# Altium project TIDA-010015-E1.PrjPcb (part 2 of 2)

## Sheet TIDA-010015-LLC.SchDoc: LLC
size 431 x 317 mm; Date: Not shown in title block; ApprovedBy: Not shown in title block; CheckedBy: Not shown in title block; Author: Not shown in title block; CompanyName: Not shown in title block; DrawnBy: Ramkumar S; Engineer: Ramkumar S; Organization: Not shown in title block; Address1: Not shown in title block; Address2: Not shown in title block; Address3: Not shown in title block; Address4: Not shown in title block; DocumentNumber: 1; Revision: Use project parameter SCH_Rev; SheetNumber: 3; SheetTotal: 4; PageSetup: Record=PageOptions¦CenterHorizontal=True¦CenterVertical=True¦PrintScale=1.00¦XCorrection=1.00¦YCorrection=1.00¦PrintKind=0¦BorderSize=5000000¦LeftOffset=0¦BottomOffset=0¦Orientation=2¦PaperLength=1000¦PaperWidth=1000¦Scale=100¦PaperSource=15¦PrintQuality=600¦MediaType=1¦DitherType=10¦PaperKind=Letter¦PrintScaleMode=1
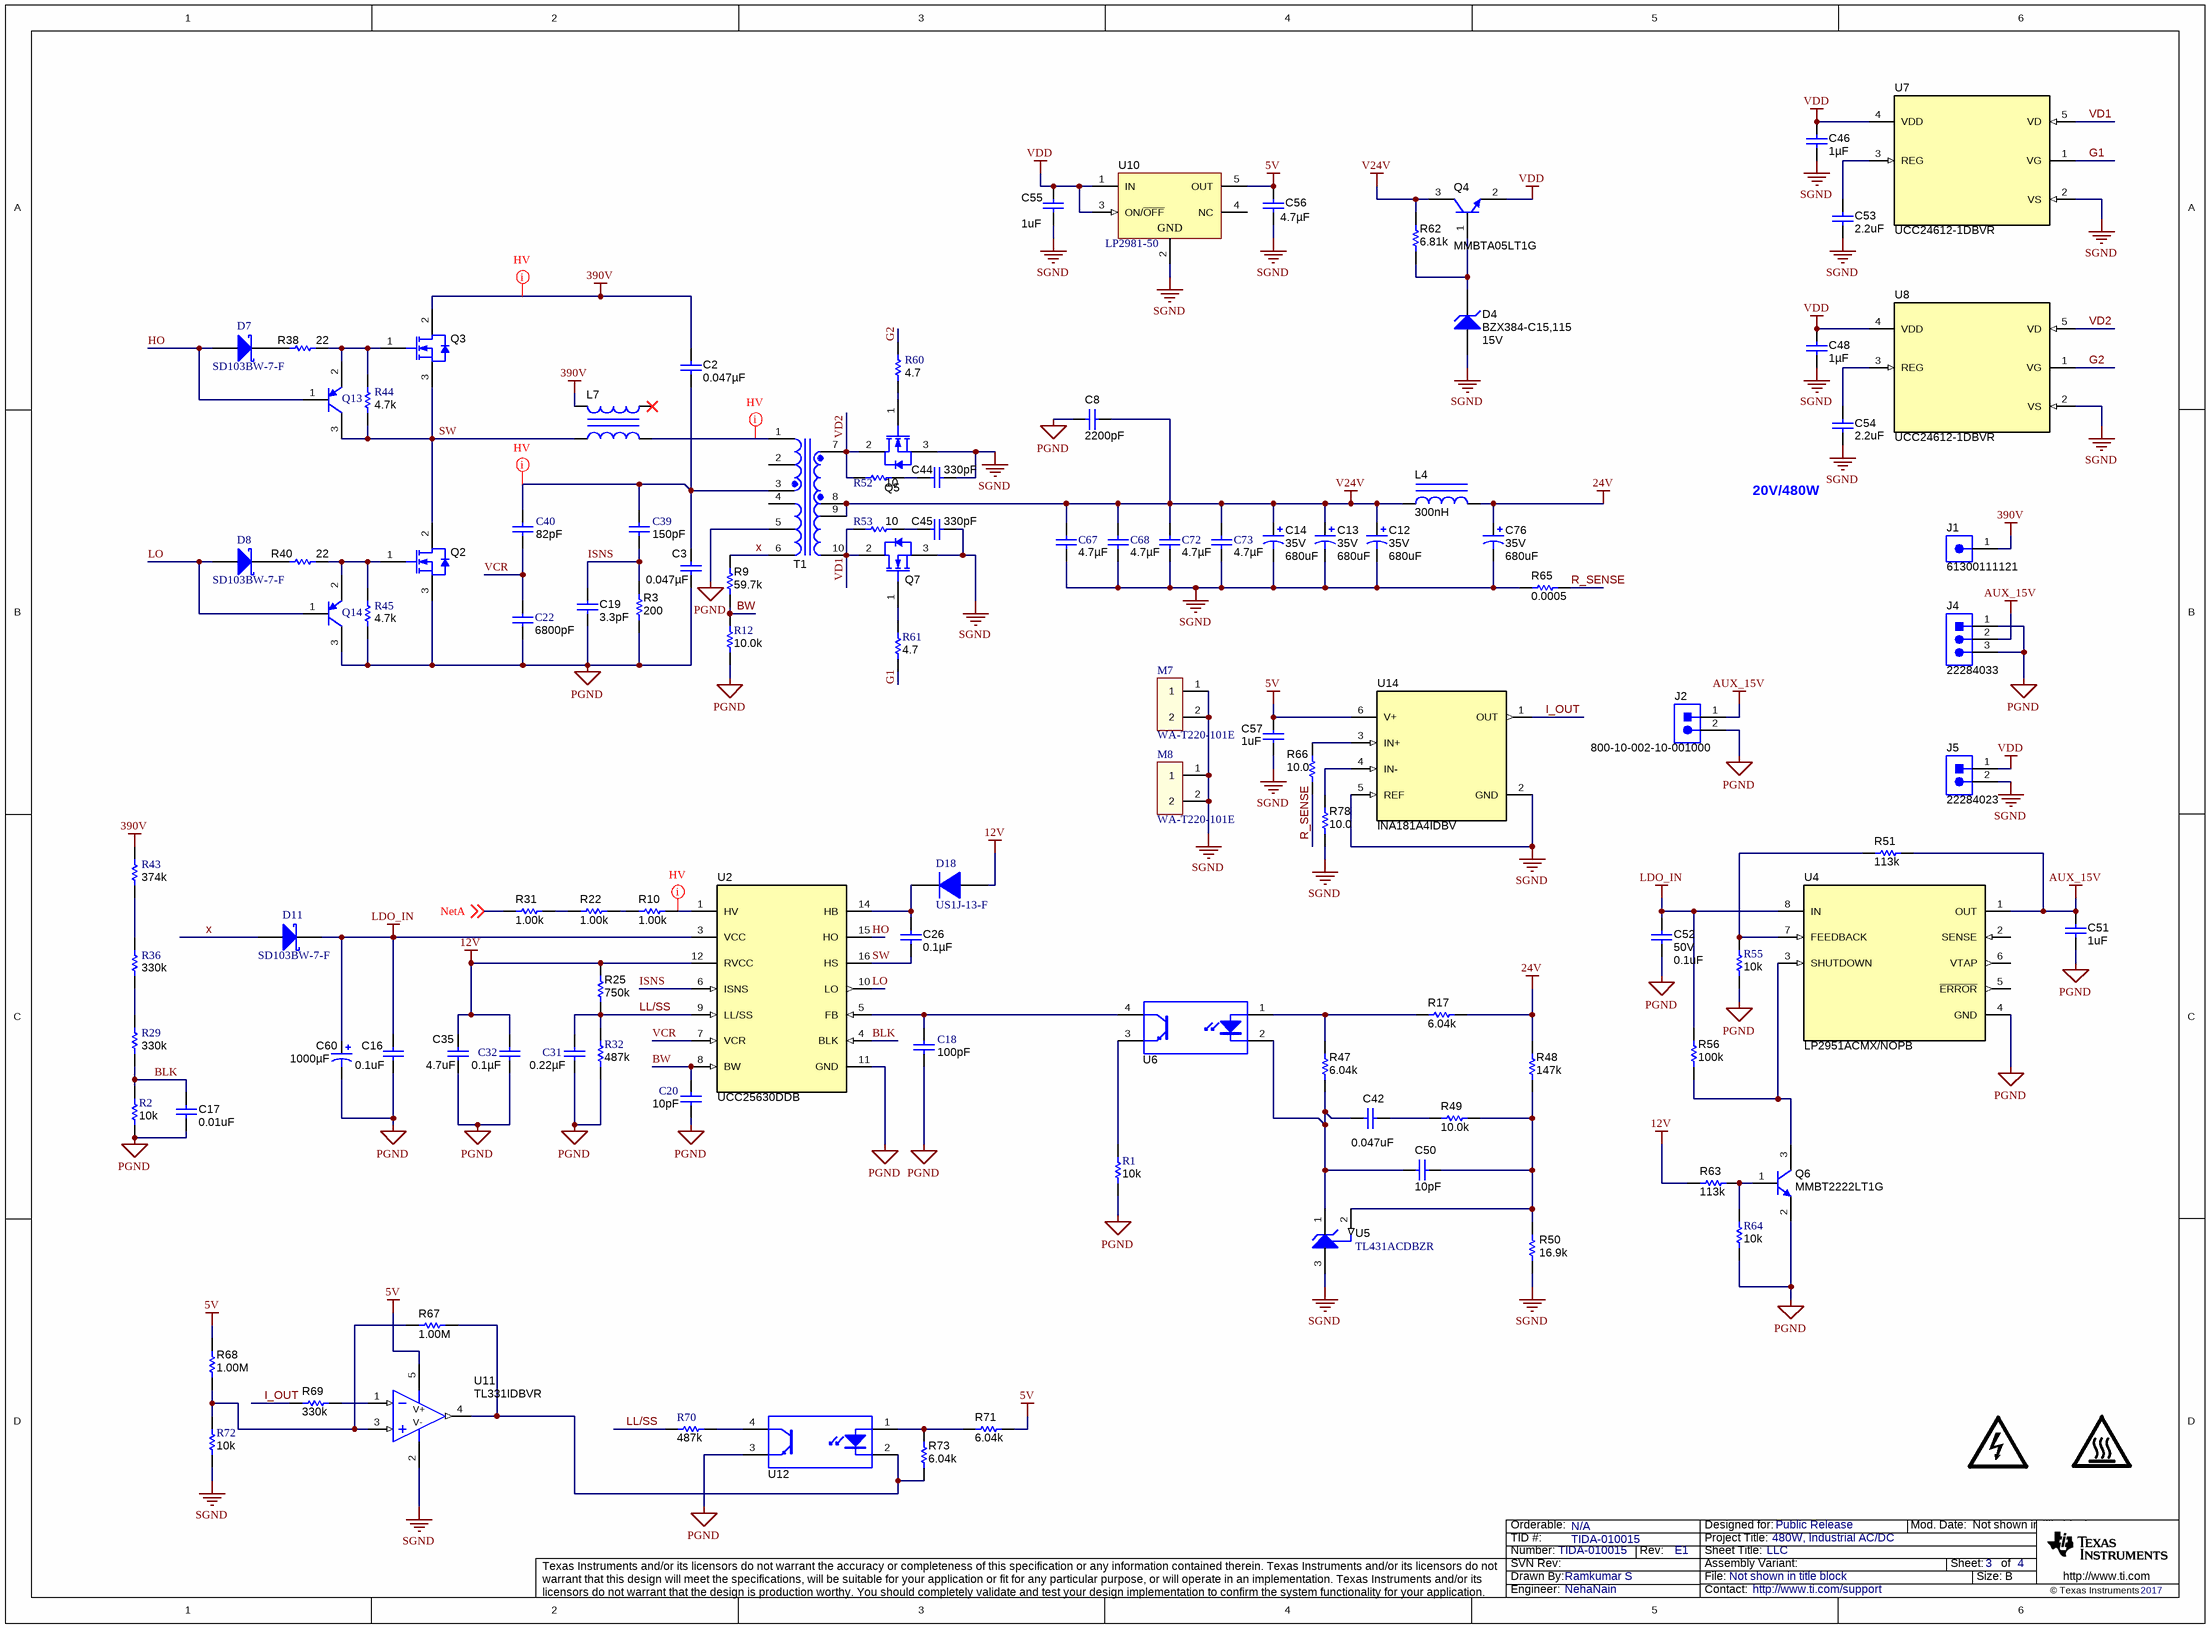
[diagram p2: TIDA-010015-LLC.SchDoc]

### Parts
(Parts that share a designator on the sheet are numbered #1, #2 ... from top to bottom, then left to right.)
C2  ValueDisplayed: 0.047µF  [B32652_1800x700x1250]  (hidden comment: B32652A0473K000)
C3  ValueDisplayed: 0.047µF  [B32652_1800x700x1250]  (hidden comment: B32652A0473K000)
C8  ValueDisplayed: 2200pF  [CD45_700x600x1100]  (hidden comment: AY2222M35Y5US63L7)
C12  VDC_V: 35V  ValueDisplayed: 680uF  [FR_1250x2000]  (hidden comment: EEU-FS1H681B)
C13  VDC_V: 35V  ValueDisplayed: 680uF  [FR_1250x2000]  (hidden comment: EEU-FS1H681B)
C14  VDC_V: 35V  ValueDisplayed: 680uF  [FR_1250x2000]  (hidden comment: EEU-FS1H681B)
C16  ValueDisplayed: 0.1uF  [0603]  (hidden comment: C1608X7R1H104K080AA)
C17  ValueDisplayed: 0.01uF  [0603]  (hidden comment: GRM188R71C103KA01D)
C18  ValueDisplayed: 100pF  [0603]  (hidden comment: 885012006023)
C19  ValueDisplayed: 3.3pF  [0805_HV1]  (hidden comment: 08055A3R3CAT2A)
C20  ValueDisplayed: 10pF  [0603]  (hidden comment: 06035A100JAT2A)
C22  ValueDisplayed: 6800pF  [0603]  (hidden comment: GRM188R71H682KA01D)
C26  ValueDisplayed: 0.1µF  [0805_HV1]  (hidden comment: C0805C104K1RACTU)
C31  ValueDisplayed: 0.22µF  [0603]  (hidden comment: 06033D224KAT2A)
C32  ValueDisplayed: 0.1µF  [0603]  (hidden comment: GRM188R72A104KA35J)
C35  ValueDisplayed: 4.7uF  [0603]  (hidden comment: GRM188R61E475KE11D)
C39  ValueDisplayed: 150pF  [1206]  (hidden comment: GRM31A7U3A151JW31D)
C40  ValueDisplayed: 82pF  [1206]  (hidden comment: GRM31A7U3A820JW31D)
C42  ValueDisplayed: 0.047uF  [0603]  (hidden comment: 06033C473JAT2A)
C44  ValueDisplayed: 330pF  [1206]  (hidden comment: 12061A331JAT2A)
C45  ValueDisplayed: 330pF  [1206]  (hidden comment: 12061A331JAT2A)
C46  ValueDisplayed: 1µF  [0805_HV1]  (hidden comment: C0805C105K3RACTU)
C48  ValueDisplayed: 1µF  [0805_HV1]  (hidden comment: C0805C105K3RACTU)
C50  ValueDisplayed: 10pF  [0603]  (hidden comment: 06035A100JAT2A)
C51  ValueDisplayed: 1uF  [1206]  (hidden comment: GRM319R61E105KC36D)
C52  VDC_V: 50V  ValueDisplayed: 0.1uF  [0603]  (hidden comment: C1608X7R1H104K080AA)
C53  ValueDisplayed: 2.2uF  [0603]  (hidden comment: GRM188R6YA225KA12D)
C54  ValueDisplayed: 2.2uF  [0603]  (hidden comment: GRM188R6YA225KA12D)
C55  ValueDisplayed: 1uF  [0603]  (hidden comment: C1608X5R1E105K080AC)
C56  ValueDisplayed: 4.7µF  [0603]  (hidden comment: GRT188R61C475KE13D)
C57  ValueDisplayed: 1uF  [0603]  (hidden comment: C1608X5R1E105K080AC)
C60  ValueDisplayed: 1000µF  [Panasonic_1000x1250]  (hidden comment: EEU-FS1V102LB)
C67  ValueDisplayed: 4.7µF  [1210]  (hidden comment: C3225X7S2A475K200AE)
C68  ValueDisplayed: 4.7µF  [1210]  (hidden comment: C3225X7S2A475K200AE)
C72  ValueDisplayed: 4.7µF  [1210]  (hidden comment: C3225X7S2A475K200AE)
C73  ValueDisplayed: 4.7µF  [1210]  (hidden comment: C3225X7S2A475K200AE)
C76  VDC_V: 35V  ValueDisplayed: 680uF  [FR_1250x2000]  (hidden comment: EEU-FS1H681B)
D4  BZX384-C15,115  value 15V  [SOD-323]
D7  SD103BW-7-F  [SOD-123]
D8  SD103BW-7-F  [SOD-123]
D11  SD103BW-7-F  [SOD-123]
D18  US1J-13-F  [SMA]
J1  61300111121  [WURTH_61300111121]
J2  800-10-002-10-001000  [Mill-Max_800-10-002-10-001000]
J4  22284033  [Molex_0022284033]
J5  22284023  [Molex_0022284023]
L4  ValueDisplayed: 300nH  [PA2607NL_7R5mm]  (hidden comment: PA2607.301NLT)
L7  (no value)  [IND_PQ2020]
LOGO?#5  DANGER HIGH VOLTAGE  [IEC_HighVoltage_Small]  (value not drawn)  (graphical)
LOGO?#6  CAUTION HOT SURFACE  [IEC_HotSurface_Small]  (value not drawn)  (graphical)
M7  WA-T220-101E  [HEATSINK_WA-T220-101E]
M8  WA-T220-101E  [HEATSINK_WA-T220-101E]
Q2  IPP60R190P6  [TO-220AB]  (value not drawn)
Q3  IPP60R190P6  [TO-220AB]  (value not drawn)
Q4  MMBTA05LT1G  [SOT-23]
Q5  CSD19505KCS  [KCS0003B]  (value not drawn)
Q6  MMBT2222LT1G  [SOT-23]
Q7  CSD19505KCS  [KCS0003B]  (value not drawn)
Q13  BC858C-7-F  [SOT-23]  (value not drawn)
Q14  BC858C-7-F  [SOT-23]  (value not drawn)
R1  ValueDisplayed: 10k  [0603]  (hidden comment: RNCF0603TKY10K0)
R2  ValueDisplayed: 10k  [0603]  (hidden comment: RNCF0603TKY10K0)
R3  ValueDisplayed: 200  [0805_HV1]  (hidden comment: RG2012P-201-B-T5)
R9  ValueDisplayed: 59.7k  [0603]  (hidden comment: RT0603BRD0759K7L)
R10  ValueDisplayed: 1.00k  [1206]  (hidden comment: CRCW12061K00FKEA)
R12  ValueDisplayed: 10.0k  [0603]  (hidden comment: CRCW060310K0FKEA)
R17  ValueDisplayed: 6.04k  [0603]  (hidden comment: CRCW06036K04FKEA)
R22  ValueDisplayed: 1.00k  [1206]  (hidden comment: CRCW12061K00FKEA)
R25  ValueDisplayed: 750k  [0603]  (hidden comment: CRCW0603750KFKEA)
R29  ValueDisplayed: 330k  [1206]  (hidden comment: CRCW1206330KJNEA)
R31  ValueDisplayed: 1.00k  [1206]  (hidden comment: CRCW12061K00FKEA)
R32  ValueDisplayed: 487k  [0603]  (hidden comment: CRCW0603487KFKEA)
R36  ValueDisplayed: 330k  [1206]  (hidden comment: CRCW1206330KJNEA)
R38  ValueDisplayed: 22  [0603]  (hidden comment: CRCW060322R0JNEA)
R40  ValueDisplayed: 22  [0603]  (hidden comment: CRCW060322R0JNEA)
R43  ValueDisplayed: 374k  [1206]  (hidden comment: CRCW1206374KFKEA)
R44  ValueDisplayed: 4.7k  [0603]  (hidden comment: CR0603-JW-472GLF)
R45  ValueDisplayed: 4.7k  [0603]  (hidden comment: CR0603-JW-472GLF)
R47  ValueDisplayed: 6.04k  [0603]  (hidden comment: CRCW06036K04FKEA)
R48  ValueDisplayed: 147k  [0603]  (hidden comment: CRCW0603147KFKEA)
R49  ValueDisplayed: 10.0k  [0603]  (hidden comment: CRCW060310K0FKEA)
R50  ValueDisplayed: 16.9k  [0603]  (hidden comment: CRCW060316K9FKEA)
R51  ValueDisplayed: 113k  [0603]  (hidden comment: CRCW0603113KFKEA)
R52  ValueDisplayed: 10  [0805_HV1]  (hidden comment: CRCW080510R0JNEA)
R53  ValueDisplayed: 10  [0805_HV1]  (hidden comment: CRCW080510R0JNEA)
R55  ValueDisplayed: 10k  [0603]  (hidden comment: RNCF0603TKY10K0)
R56  ValueDisplayed: 100k  [0603]  (hidden comment: RT0603BRD07100KL)
R60  ValueDisplayed: 4.7  [0805_HV1]  (hidden comment: CRCW08054R70JNEA)
R61  ValueDisplayed: 4.7  [0805_HV1]  (hidden comment: CRCW08054R70JNEA)
R62  ValueDisplayed: 6.81k  [0603]  (hidden comment: RC0603FR-076K81L)
R63  ValueDisplayed: 113k  [0603]  (hidden comment: CRCW0603113KFKEA)
R64  ValueDisplayed: 10k  [0603]  (hidden comment: RNCF0603TKY10K0)
R65  ValueDisplayed: 0.0005  [WSL2512_-0005]  (hidden comment: WSL2512L5000FEA18)
R66  ValueDisplayed: 10.0  [0603]  (hidden comment: CRCW060310R0FKEAHP)
R67  ValueDisplayed: 1.00M  [0805_HV]  (hidden comment: CRCW08051M00FKEA)
R68  ValueDisplayed: 1.00M  [0603]  (hidden comment: MCT06030C1004FP500)
R69  ValueDisplayed: 330k  [0603]  (hidden comment: ERJ-3EKF3303V)
R70  ValueDisplayed: 487k  [0603]  (hidden comment: CRCW0603487KFKEA)
R71  ValueDisplayed: 6.04k  [0603]  (hidden comment: CRCW06036K04FKEA)
R72  ValueDisplayed: 10k  [0603]  (hidden comment: RNCF0603TKY10K0)
R73  ValueDisplayed: 6.04k  [0603]  (hidden comment: CRCW06036K04FKEA)
R78  ValueDisplayed: 10.0  [0603]  (hidden comment: CRCW060310R0FKEAHP)
T1  PQ3230  [IND_PQ3230]  (value not drawn)
U2  UCC25630DDB  [DDB0014A]
U4  LP2951ACMX/NOPB  [D0008A_L]
U5  TL431ACDBZR  [DBZ0003A_N]
U6  VO618A  [DIP-4]  (value not drawn)
U7  UCC24612-1DBVR  [DBV0005A_N]
U8  UCC24612-1DBVR  [DBV0005A_N]
U10  LP2981-50  [DBV0005A_N]
U11  TL331IDBVR  [DBV0005A_N]
U12  VO618A  [DIP-4]  (value not drawn)
U14  INA181A4IDBV  [DBV0006A_N]

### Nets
5V: C56.1 C57.1 R68.2 R71.2 U10.5(OUT) U11.5(V+) U14.6(V+)
12V: C32.1 C35.2 D18.2(A) R25.2 R63.1 U2.12(RVCC)
24V: C76.1(+) L4.2 R17.2 R48.2
390V: C2.1 J1.1 L7.3 Q3.2(D) R43.2
AUX_15V: C51.1 J2.1 J4.2 R51.2 U4.1(OUT)
LDO_IN: C16.1 C52.1 C60.1(+) D11.1(K) R56.2 U2.3(VCC) U4.8(IN)
PGND: C3.2 C8.2 C16.2 C17.2 C18.2 C19.2 C20.2 C22.2 C31.2 C32.2 C35.1 C51.2 C52.2 C60.2(-) J2.2 J4.1 J4.3 Q2.3(S) Q6.2(E) Q14.3(C) R1.1 R2.1 R3.1 R12.1 R32.1 R45.1 R55.1 R64.1 T1.5 U2.11(GND) U4.4(GND) U12.3(E)
SGND: C12.2(-) C13.2(-) C14.2(-) C44.1 C45.1 C46.2 C48.2 C53.2 C54.2 C55.2 C56.2 C57.2 C67.2 C68.2 C72.2 C73.2 C76.2(-) D4.2(A) J5.2 M7.1 M7.2 M8.1 M8.2 Q5.3(S) Q7.3(S) R50.1 R65.1 R72.1 R78.1 U5.3(ANODE) U7.2(VS) U8.2(VS) U10.2(GND) U11.2(V-/GND) U14.2(GND) U14.5(REF)
V24V: C8.1 C12.1(+) C13.1(+) C14.1(+) C67.1 C68.1 C72.1 C73.1 L4.1 Q4.3(C) R62.2 T1.8 T1.9
VDD: C46.1 C48.1 C55.1 J5.1 Q4.2(E) U7.4(VDD) U8.4(VDD) U10.1(IN) U10.3(ON/~{OFF})
BLK: C17.1 R2.2 R29.1 U2.4(BLK)
BW: C20.1 R9.1 R12.2 U2.8(BW)
G1: R61.1 U7.1(VG)
G2: R60.2 U8.1(VG)
HO: D7.2(A) Q13.1(B) U2.15(HO)
I_OUT: R69.1 U14.1(OUT)
ISNS: C19.1 C39.2 R3.2 U2.6(ISNS)
LL/SS: C31.1 R25.1 R32.2 R70.2 U2.9(LL/SS)
LO: D8.2(A) Q14.1(B) U2.10(LO)
NetA: R31.1 ; off-sheet NetA
R_SENSE: R65.2 R66.1
SW: C26.2 L7.1 Q2.2(D) Q3.3(S) Q13.3(C) R44.1 U2.16(HS)
VCR: C22.1 C40.2 U2.7(VCR)
VD1: Q7.2(D) R53.1 T1.10 U7.5(VD)
VD2: Q5.2(D) R52.1 T1.7 U8.5(VD)
x: D11.2(A) R9.2 T1.6
NetC2_2: C2.2 C3.1 C39.1 C40.1 T1.3
NetC18_1: C18.1 U2.5(FB) U6.4(C)
NetC26_1: C26.1 D18.1(K) U2.14(HB)
NetC42_1: C42.1 R49.1
NetC42_2: C42.2 C50.2 R47.1 U5.1(CATHODE) U6.2(K)
NetC44_2: C44.2 R52.2
NetC45_2: C45.2 R53.2
NetC50_1: C50.1 R48.1 R49.2 R50.2 U5.2(REF)
NetC53_1: C53.1 U7.3(REG)
NetC54_1: C54.1 U8.3(REG)
NetD4_1: D4.1(K) Q4.1(B) R62.1
NetD7_1: D7.1(K) R38.1
NetD8_1: D8.1(K) R40.1
NetL7_2: L7.2 T1.1
NetQ2_1: Q2.1(G) Q14.2(E) R40.2 R45.2
NetQ3_1: Q3.1(G) Q13.2(E) R38.2 R44.2
NetQ5_1: Q5.1(G) R60.1
NetQ6_1: Q6.1(B) R63.2 R64.2
NetQ6_3: Q6.3(C) R56.1 U4.3(SHUTDOWN)
NetQ7_1: Q7.1(G) R61.2
NetR1_2: R1.2 U6.3(E)
NetR10_1: R10.1 R22.2
NetR10_2: R10.2 U2.1(HV)
NetR17_1: R17.1 R47.2 U6.1(A)
NetR22_1: R22.1 R31.2
NetR29_2: R29.2 R36.1
NetR36_2: R36.2 R43.1
NetR51_1: R51.1 R55.2 U4.7(FEEDBACK)
NetR66_2: R66.2 U14.3(IN+)
NetR67_1: R67.1 R68.1 R72.2 U11.3(IN+)
NetR67_2: R67.2 R73.1 U11.4(OUT) U12.2(K)
NetR69_2: R69.2 U11.1(IN-)
NetR70_1: R70.1 U12.4(C)
NetR71_1: R71.1 R73.2 U12.1(A)
NetR78_2: R78.2 U14.4(IN-)

Not connected (* = marked no-connect by the designer): L7 4*; T1 2 4; U4 2(SENSE) 5(~{ERROR}) 6(VTAP); U10 4(NC)

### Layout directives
net class HV: 390V, NetC2_2, NetL7_2, NetR10_2

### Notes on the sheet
- 20V/480W

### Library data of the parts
C2 C3 = B32652A7153J000: CAP FILM 0.047UF 10% 1KVDC RAD; Manufacturer: EPCOS (TDK); Polarized: N; CompType: Capacitor; U/M: EA; Cap_F: 0.000000047; Tolerance_%: 5; VDC_V: 1250; Value2: 1250V; TaMin_C: -55; TaMax_C: 100; Cap_Case: 18x7x12.5; SizeAreaWB_mm2: 180; SizeArea_mm2: 126; SizeX_mm: 18; SizeY_mm: 7; SizeZ_mm: 12.5; AEC Category: Q200; AEC Qualified: Y; AEC Grade: 3; Green_Lifecycle: Not Set; Green_REACh: Incomplete; VAC: 250
C8 = AY2222M35Y5US63L7: CAP, CERM, 2200 pF, 300 V, +/- 20%, Y5U, AEC-Q200 Grade 1, D9.5xT5mm; Manufacturer: Vishay-Bccomponents; Polarized: N; CompType: Capacitor; Value: 2200pF; U/M: EA; Cap_F: 0.0000000022; Tolerance_%: 20; Value1: Unknown; VDC_V: 300; Value2: 300V; TaMin_C: -55; TaMax_C: 125; Cap_Case: 9.5x5mm; SizeArea_mm2: 47.5; SizeAreaWB_mm2: 80.5; SizeX_mm: 9.5; SizeY_mm: 5; SizeZ_mm: 14.5; AEC Category: Q200; AEC Qualified: Y; AEC Grade: 1
C12-C14 C76 = CMP-0010351-2: 680µF 50V Aluminum Electrolytic Capacitors Radial, Can 10000 Hrs @ 105°C; Manufacturer: Panasonic Electronic Components; TaMin_C: -45°C; Polarized: Y; U/M: EA; Value: 680uF; Tolerance_%: 20%; SizeZ_mm: 22; SizeX_mm: 12.5; AEC Qualified: N
C16 = CMP-0007044-5: CAP, CERM, 0.1 uF, 50 V, +/- 10%, X7R, 0603; Manufacturer: TDK; TaMin_C: -55°C; ESR_ohm: 0.0296; Polarized: N; SizeAreaWB_mm2: 4.68; Value1: 0.0296 ohm; U/M: EA; Value: 0.1uF; TaMax_C: 125°C; SizeZ_mm: 1; SizeX_mm: 1.6; SizeY_mm: 0.8; Value2: 50V; SizeArea_mm2: 1.28; CompType: Capacitor; Cap_F: 100nF; IRMS_A: 9.7199dA; AEC Category: Q200
C17 = CMP-0007377-4: CAP, CERM, 0.01 uF, 16 V, +/- 10%, X7R, 0603; Manufacturer: MuRata; TaMin_C: -55°C; Polarized: N; SizeAreaWB_mm2: 4.68; Value1: Unknown; U/M: EA; Value: 0.01uF; TaMax_C: 125°C; SizeZ_mm: 1; SizeX_mm: 1.6; Value2: 16V; SizeArea_mm2: 1.28; CompType: Capacitor; Cap_F: 10nF; AEC Category: Q200; SizeY_mm: 0.8
C18 = C0603C101J5GAC: CAP CER 100PF 16V C0G/NP0 0603; Manufacturer: Wurth Electronics Inc.; Polarized: N; CompType: Capacitor; U/M: EA; Cap_F: 0.0000000001; Tolerance_%: 5; Value1: Unknown; VDC_V: 16; TaMin_C: -55; TaMax_C: 125
C19 = 08055A3R3CAT2A: CAP, CERM, 3.3 pF, 50 V, +/- 8%, C0G/NP0, 0805; Manufacturer: AVX; Polarized: N; CompType: Capacitor; Value: 3.3pF; U/M: EA; Cap_F: 0.0000000000033; Tolerance_%: 8; ESR_ohm: 3.467; Value1: 3.467 ohm; VDC_V: 50; Value2: 50V; TaMin_C: -55; TaMax_C: 125; Cap_Case: 0805; SizeArea_mm2: 2.5; SizeAreaWB_mm2: 6.75; SizeX_mm: 2; SizeY_mm: 1.25; SizeZ_mm: 1.45; AEC Category: Q200; Green_Lifecycle: Not Set; Green_REACh: Incomplete
C20 = 06035A100JAT2A: CAP, CERM, 10 pF, 50 V, +/- 5%, C0G/NP0, 0603; Manufacturer: AVX; Polarized: N; CompType: Capacitor; Value: 10pF; U/M: EA; Cap_F: 0.00000000001; Tolerance_%: 5; ESR_ohm: 0.403; Value1: 0.403 ohm; VDC_V: 50; Value2: 50V; TaMin_C: -55; TaMax_C: 125
C22 = GRM188R71H682KA01D: CAP, CERM, 6800 pF, 50 V, +/- 10%, X7R, 0603; Manufacturer: MuRata; Polarized: N; CompType: Capacitor; Value: 6800pF; U/M: EA; Cap_F: 0.0000000068; Tolerance_%: 10; Value1: Unknown; VDC_V: 50; Value2: 50V; TaMin_C: -55; TaMax_C: 125
C26 = C0805C104K1RACTU: CAP, CERM, 0.1 µF, 100 V,+/- 10%, X7R, 0805; Manufacturer: Kemet; Polarized: N; CompType: Capacitor; Value: 0.1uF; U/M: EA; Cap_F: 0.0000001; Tolerance_%: 10; ESR_ohm: 0.064; Value1: 0.064 ohm; VDC_V: 100; Value2: 100V; IRMS_A: 1.64; TaMin_C: -55; TaMax_C: 125; Cap_Case: 0805; SizeArea_mm2: 2.5; SizeAreaWB_mm2: 6.75; SizeX_mm: 2; SizeY_mm: 1.25; SizeZ_mm: 1.45; AEC Category: Q200; Green_Lifecycle: Active; Green_REACh: Passed
C31 = 06033D224KAT2A: CAP, CERM, 0.22 µF, 25 V, +/- 10%, X5R, 0603; Manufacturer: AVX; Polarized: N; CompType: Capacitor; Value: 0.22uF; U/M: EA; Cap_F: 0.00000022; Tolerance_%: 10; ESR_ohm: 0.036; Value1: 0.036 ohm; VDC_V: 25; Value2: 25V; TaMin_C: -55; TaMax_C: 85
C32 = GRM188R72A104KA35J: CAP, CERM, 0.1 µF, 100 V, +/- 10%, X7R, 0603; Manufacturer: MuRata; Polarized: N; CompType: Capacitor; Value: 0.1uF; U/M: EA; Cap_F: 0.0000001; Tolerance_%: 10; Value1: Unknown; VDC_V: 100; Value2: 100V; TaMin_C: -55; TaMax_C: 125
C35 = CMP-0007347-5: CAP, CERM, 4.7 uF, 25 V, +/- 10%, X5R, 0603; Manufacturer: MuRata; TaMin_C: -55°C; Polarized: N; SizeAreaWB_mm2: 4.68; Value1: Unknown; U/M: EA; Value: 4.7uF; TaMax_C: 85°C; SizeZ_mm: 1; SizeX_mm: 1.6; SizeY_mm: 0.8; Value2: 25V; SizeArea_mm2: 1.28; CompType: Capacitor; Cap_F: 4.7µF; AEC Category: Q200
C39 = GRM31A7U3A151JW31D: CAP, CERM, 150 pF, 1000 V, +/- 5%, U2J, 1206; Manufacturer: MuRata; Polarized: N; CompType: Capacitor; Value: 150pF; U/M: EA; Cap_F: 0.00000000015; Tolerance_%: 5; Value1: Unknown; VDC_V: 1000; Value2: 1000V; TaMin_C: -55; TaMax_C: 125
C40 = GRM31A7U3A151JW31D: CAP CER 82PF 1KV U2J 1206; Manufacturer: MuRata; Polarized: N; CompType: Capacitor; U/M: EA; Cap_F: 0.000000000082; Tolerance_%: 5; Value1: Unknown; VDC_V: 1000; Value2: 1000V; TaMin_C: -55; TaMax_C: 125
C42 = CMP-0006757-5: CAP, CERM, 0.047 uF, 25 V, +/- 5%, X7R, 0603; Manufacturer: AVX; TaMin_C: -55°C; ESR_ohm: 0.052; Polarized: N; SizeAreaWB_mm2: 4.68; Value1: 0.052 ohm; U/M: EA; TaMax_C: 125°C; SizeZ_mm: 1; SizeX_mm: 1.6; SizeY_mm: 0.8; Value2: 25V; SizeArea_mm2: 1.28; CompType: Capacitor; Cap_F: 47nF; AEC Category: Q200
C44 C45 = CMP-0008475-2: CAP, CERM, 330 pF, 100 V, +/- 5%, C0G/NP0, 1206; Manufacturer: AVX; TaMin_C: -55°C; ESR_ohm: 3.92d; Polarized: N; SizeAreaWB_mm2: 10.92; Value1: 0.392 ohm; U/M: EA; Value: 330pF; TaMax_C: 125°C; SizeZ_mm: 1.35; SizeX_mm: 3.2; SizeY_mm: 1.6; Value2: 100V; SizeArea_mm2: 5.12; CompType: Capacitor; AEC Category: Q200
C46 C48 = C0805C105K3RACTU: CAP, CERM, 1 µF, 25 V, +/- 10%, X7R, 0805; Manufacturer: Kemet; Polarized: N; CompType: Capacitor; Value: 1uF; U/M: EA; Cap_F: 0.000001; Tolerance_%: 10; Value1: Unknown; VDC_V: 25; Value2: 25V; TaMin_C: -55; TaMax_C: 125; Cap_Case: 0805; SizeArea_mm2: 2.5; SizeAreaWB_mm2: 6.75; SizeX_mm: 2; SizeY_mm: 1.25; SizeZ_mm: 1.45; AEC Category: Q200; Green_Lifecycle: Active; Green_REACh: Passed
C50 = 06035A100JAT2A: CAP, CERM, 10 pF, 50 V,+/- 5%, C0G/NP0, 0603; Manufacturer: AVX; Polarized: N; CompType: Capacitor; Value: 10pF; U/M: EA; Cap_F: 0.00000000001; Tolerance_%: 5; ESR_ohm: 0.403; Value1: 0.403 ohm; VDC_V: 50; Value2: 50V; TaMin_C: -55; TaMax_C: 125; SizeArea_mm2: 1.28; SizeAreaWB_mm2: 4.68; SizeX_mm: 1.6; SizeY_mm: 0.8; SizeZ_mm: 1; AEC Category: Q200; Green_Lifecycle: Active; Green_REACh: Passed
C51 = GRM319R61E105KC36D: CAP, CERM, 1uF, 25V, +/-10%, X5R, 1206; Manufacturer: MuRata; Polarized: N; CompType: Capacitor; U/M: EA; Cap_F: 0.000001; Tolerance_%: 10; ESR_Ohm: 0.01; Value1: 0.01 ohm; VDC_V: 25; TaMin_C: -55; TaMax_C: 85
C52 = CMP-0007044-5: CAP, CERM, 0.1 uF, 50 V, +/- 10%, X7R, 0603; Manufacturer: TDK; TaMin_C: -55°C; ESR_ohm: 0.0296; Polarized: N; SizeAreaWB_mm2: 4.68; Value1: 0.0296 ohm; U/M: EA; Value: 0.1uF; TaMax_C: 125°C; SizeZ_mm: 1; SizeX_mm: 1.6; SizeY_mm: 0.8; SizeArea_mm2: 1.28; Cap_F: 100nF; IRMS_A: 9.7199dA; AEC Category: Q200
C53 C54 = CMP-0007356-5: CAP, CERM, 2.2 uF, 35 V, +/- 10%, X5R, 0603; Manufacturer: MuRata; TaMin_C: -55°C; Polarized: N; SizeAreaWB_mm2: 4.68; Value1: Unknown; U/M: EA; Value: 2.2uF; TaMax_C: 85°C; SizeZ_mm: 1; SizeX_mm: 1.6; SizeY_mm: 0.8; Value2: 35V; SizeArea_mm2: 1.28; CompType: Capacitor; Cap_F: 2.2µF; AEC Category: Q200
C55 C57 = CMP-0007006-5: CAP, CERM, 1 uF, 25 V, +/- 10%, X5R, 0603; Manufacturer: TDK; TaMin_C: -55°C; Polarized: N; SizeAreaWB_mm2: 4.68; Value1: Unknown; U/M: EA; Value: 1uF; TaMax_C: 85°C; SizeZ_mm: 1; SizeX_mm: 1.6; SizeY_mm: 0.8; Value2: 25V; SizeArea_mm2: 1.28; CompType: Capacitor; Cap_F: 1µF; AEC Category: Q200
C56 = CMP-0081052-1: CAP, CERM, 4.7 µF, 16 V,+/- 10%, X5R, AEC-Q200 Grade 3, 0603; Manufacturer: MuRata; SizeAreaWB_mm2: 4.68; SizeArea_mm2: 1.28; AEC Qualified: Y; AEC Category: Q200; Value: 4.7uF; TaMax_C: 85°C; SizeZ_mm: 1; AEC Grade: 3; Polarized: N; TaMin_C: -55°C; VDC_V: 16V; SizeY_mm: 0.8; U/M: EA; CompType: Capacitor; SizeX_mm: 1.6
C60 = CMP-0064896-2: 1000µF 35V Aluminum Electrolytic Capacitors Radial, Can 10000 Hrs @ 105°C; Manufacturer: Panasonic; TaMin_C: -55°C; ESR_ohm: 1.62d; Polarized: Y; SizeAreaWB_mm2: 144; U/M: EA; Tolerance_%: 20%; SizeZ_mm: 14; SizeX_mm: 10; Cap_Case: 10x12.5; SizeArea_mm2: 100; Cap_F: 100µF; IRMS_A: 6.15dA; AEC Grade: 2; AEC Category: Q200
C67 C68 C72 C73 = C3225X7S2A475K200AE: CAP, CERM, 4.7 µF, 100 V, +/- 10%, X7S, 1210; Manufacturer: TDK; Polarized: N; CompType: Capacitor; Value: 4.7uF; U/M: EA; Cap_F: 0.0000047; Tolerance_%: 10; Value1: Unknown; VDC_V: 100; Value2: 100V; TaMin_C: -55; TaMax_C: 125
D4 = CMP-0005844-2: Diode, Zener, 15 V, 300 mW, SOD-323; Manufacturer: NXP Semiconductor; Power_W: 300mW; SizeAreaWB_mm2: 8.695; Value1: 0.3W; RJA_CperW: 415; U/M: EA; SizeZ_mm: 1; SizeX_mm: 2.7; SizeY_mm: 1.35; SizeArea_mm2: 3.645; AEC Category: Q101
D7 D8 D11 = SD103BW-7-F: Diode, Schottky, 30 V, 0.35 A, SOD-123; Manufacturer: Diodes Inc.; U/M: EA; Vf_V: 0.55; Value: 30V; Value1: 0.35A; Value2: 0.55V; Io_A: 0.35; Vr_V: 30
D18 = US1J-13-F: Diode, Ultrafast, 600 V, 1 A, SMA; Manufacturer: Diodes Inc.; U/M: EA; Vf_V: 1.7; Value: 600V; Value1: 1A; Value2: 1.7V; Io_A: 1; Vr_V: 600; TJmax_C: 150
J1 = CMP-0054792-1: Header, 2.54 mm, 1x1, Gold, TH; Manufacturer: Wurth Elektronik; CNHeader: TRUE; CT: FALSE
J2 = CMP-0055085-1: Header, 100mil, 2x1, TH; Manufacturer: Mill-Max; CNHeader: TRUE; Green_Lifecycle: Active; Green_REACh: Passed; CT: FALSE
J4 = CMP-0055332-1: Header, 2.54mm, 3x1, Tin, TH; Manufacturer: Molex; CNHeader: TRUE; Current_A: 4A; Shrouded: N; Gender: Male; Voltage_V: 250V; Row_Count: 1; Pitch_mm: 2.54; CT: FALSE; Cert_UL: Y
J5 = CMP-0055333-1: Header, 2.54mm, 2x1, Tin, TH; Manufacturer: Molex; CNHeader: TRUE; Current_A: 4A; Shrouded: N; Gender: Male; Voltage_V: 250V; Row_Count: 1; Pitch_mm: 2.54; CT: FALSE; Cert_UL: Y
L4 = CMP-0062077-1: Inductor, Ferrite, 300 nH, 32 A, 0.00031 ohm, SMD; Manufacturer: Pulse Engineering; Isat: 32A @ 20% inductance drop; Irms: 41A @ 40C rise; SizeAreaWB_mm2: 118.7915; DCR_ohm: 310µ; Value: 300nH; Imax_A: 32A; SizeZ_mm: 7.5; SizeX_mm: 7.65; SizeY_mm: 10.31; SizeArea_mm2: 78.8715; AEC Qualified: N; AEC Category: Q200
L7 = 1140-331K-RC: Inductor, Ferrite, 330 µH, 6.1 A, 0.074 ohm, TH; DCR_ohm: 0.074; AEC Category: Q200
LOGO?#5 = IEC_HighVoltage: IEC 61010-1 High Voltage Warning; SymbolCreator: a0412235
LOGO?#6 = IEC_HotSurface: IEC 61010-1 Hot Surface Warning; SymbolCreator: a0412235
M7 M8 = WA-T220-101E: HEATSINK, ALUMINIUM WITH CLIP, VERTICAL MOUNT, SOLDERABLE PIN, TO-220; Manufacturer: OHMITE; SymbolCreator: x0199378
Q2 Q3 = CMP-0001223-3: MOSFET N-CHANNEL 600V 26A TO220; PartNumber: IPA60R120P7XKSA1; Alternate Manufacturer: None; Manufacturer: Infineon Technologies; SizeZ_mm: 19.4; ChType: N; Value2: 37 nC; VdsMax_V: 650V; SizeX_mm: 10.2; SizeY_mm: 4.5; Vgs_V: 20V; QgTyp_nC: 37; Value: 650V; SizeArea_mm2: 45.9; AEC Category: Q101; IdsMax_A: 20.2A; SizeAreaWB_mm2: 79.3; U/M: EA
Q4 = CMP-0000488-2: Transistor, NPN, 60 V, 0.5 A, AEC-Q101, SOT-23; Manufacturer: ON Semiconductor; TaMax_C: 150°C; Value1: 0.5 A; Vcesat1_V: 2.5dV; SizeX_mm: 2.5; SizeY_mm: 3; TaMin_C: -55°C; IcRated_A: 5dA; CompType: BJT; SizeZ_mm: 1.1; AEC Qualified: Y; Value: 60 V; SizeArea_mm2: 7.5; NPN: 1; Vceo_V: 60V; PNP: 0; AEC Category: Q101; SizeAreaWB_mm2: 14; U/M: EA
Q5 Q7 = CMP-0000914-1: MOSFET, N-CH, 80 V, 100 A, KCS0003B (TO-220-3); PartNumber: CSD19501KCS; Alternate Manufacturer: None; Manufacturer: Texas Instruments; SizeZ_mm: 20.45; ChType: N; Value2: 38 nC; VdsMax_V: 80V; SizeX_mm: 4.55; SizeY_mm: 10.16; Vgs_V: 20V; Value: 80V; SizeArea_mm2: 46.228; AEC Category: Q101; IdsMax_A: 100A; SizeAreaWB_mm2: 79.648; U/M: EA; QgTyp_nC: 38
Q6 = CMP-0000421-2: Transistor, NPN, 30 V, 0.6 A, SOT-23; Manufacturer: ON Semiconductor; TaMax_C: 150°C; Value2: 300; Value1: 0.6 A; Vcesat1_V: 1.6V; SizeX_mm: 2.5; SizeY_mm: 3; TaMin_C: -55°C; IcRated_A: 6dA; CompType: BJT; SizeZ_mm: 1.1; Value: 30 V; SizeArea_mm2: 7.5; NPN: 1; Vceo_V: 30V; PNP: 0; AEC Category: Q101; SizeAreaWB_mm2: 14; U/M: EA
Q13 Q14 = BC858C-7-F, Diodes Inc.: Transistor, PNP, 30 V, 0.1 A, SOT-23; CompType: BJT; PNP: 1; NPN: 0; Vceo_V: 30; Vcesat1_V: 0.075; Value: 30 V; IcRated_A: 0.1; Value1: 0.1 A; HfeMax: 600; TaMin_C: -65; TaMax_C: 150; U/M: EA
R1 R2 R55 R64 R72 = RNCF0603TKY10K0: RES, 10 k, 0.01%, 0.063 W, 0603; Manufacturer: Stackpole Electronics Inc; CompType: Resistor; Value: 10k; Res_ohm: 10000; Value_Code: 10k0; Tolerance_%: 0.01; Power_W: 0.063; Value2: 0.063W; VDC_V: 50; TempCo: 5 ppm/C; U/M: EA
R3 = CMP-0018911-2: RES, 200, 0.1%, 0.125 W, 0805; Manufacturer: Susumu Co Ltd; Power_W: 125mW; TempCo: 25 ppm/C; Value_Code: 200R; U/M: EA; Value: 200; EIA_Code: E192; SizeX_mm: 2; SizeY_mm: 1.25; SizeZ_mm: 1.45; Value2: 0.125W; SizeArea_mm2: 2.5; CompType: Resistor; VDC_V: 100V; AEC Category: Q200
R9 = CMP-0024361-3: RES, 59.7 k, 0.1%, 0.1 W, 0603; Manufacturer: Yageo America; Power_W: 100mW; TempCo: 25 ppm/C; Value_Code: 59k7; U/M: EA; Value: 59.7k; EIA_Code: E192; SizeX_mm: 1.6; SizeY_mm: 0.8; SizeZ_mm: 1; Value2: 0.1W; SizeArea_mm2: 1.28; CompType: Resistor; VDC_V: 75V; AEC Category: Q200
R10 R22 R31 = CRCW12061K00FKEA: RES, 1.00 k, 1%, 0.25 W, 1206; Manufacturer: Vishay-Dale; CompType: Resistor; Value: 1.00k; Res_ohm: 1000; Value_Code: 1k00; Tolerance_%: 1; Power_W: 0.25; Value2: 0.25W; VDC_V: 200; TempCo: 100 ppm/C; SizeArea_mm2: 5.12; SizeX_mm: 3.2; SizeY_mm: 1.6; SizeZ_mm: 1.35; EIA_Code: E96; U/M: EA; AEC Category: Q200; Green_Lifecycle: Active; Green_REACh: Passed
R12 = CRCW060310K0FKEA: RES, 10.0 k, 1%, 0.1 W, 0603; Manufacturer: Vishay-Dale; CompType: Resistor; Value: 10.0k; Res_ohm: 10000; Value_Code: 10k0; Tolerance_%: 1; Power_W: 0.1; Value2: 0.1W; VDC_V: 75; TempCo: 100 ppm/C; EIA_Code: E96; U/M: EA
R17 R47 R71 R73 = CRCW06036K04FKEA: RES, 6.04 k, 1%, 0.1 W, 0603; Manufacturer: Vishay-Dale; CompType: Resistor; Value: 6.04k; Res_ohm: 6040; Value_Code: 6k04; Tolerance_%: 1; Power_W: 0.1; Value2: 0.1W; VDC_V: 75; TempCo: 100 ppm/C; SizeArea_mm2: 1.28; SizeX_mm: 1.6; SizeY_mm: 0.8; EIA_Code: E96; U/M: EA; AEC Category: Q200; Green_Lifecycle: Active; Green_REACh: Passed
R25 = CRCW0603750KFKEA: RES, 750 k, 1%, 0.1 W, 0603; Manufacturer: Vishay-Dale; CompType: Resistor; Value: 750k; Res_ohm: 750000; Tolerance_%: 1; Power_W: 0.1; Value2: 0.1W; VDC_V: 75; TempCo: 100 ppm/C; SizeArea_mm2: 1.28; SizeX_mm: 1.6; SizeY_mm: 0.8; EIA_Code: E96; U/M: EA; AEC Category: Q200; Green_Lifecycle: Active; Green_REACh: Passed
R29 R36 = CRCW1206330KJNEA: RES, 330 k, 5%, 0.25 W, 1206; Manufacturer: Vishay-Dale; CompType: Resistor; Value: 330k; Res_ohm: 330000; Tolerance_%: 5; Power_W: 0.25; Value2: 0.25W; VDC_V: 200; TempCo: 200 ppm/C; EIA_Code: E24; U/M: EA
R32 R70 = CRCW0603487KFKEA: RES, 487 k, 1%, 0.1 W, 0603; Manufacturer: Vishay-Dale; CompType: Resistor; Value: 487k; Res_ohm: 487000; Tolerance_%: 1; Power_W: 0.1; Value2: 0.1W; VDC_V: 75; TempCo: 100 ppm/C; EIA_Code: E96; U/M: EA
R38 R40 = CRCW060322R0JNEA: RES, 22, 5%, 0.1 W, 0603; Manufacturer: Vishay-Dale; CompType: Resistor; Value: 22; Value_Code: 22R0; Tolerance_%: 5; Power_W: 0.1; Value2: 0.1W; VDC_V: 75; TempCo: 200 ppm/C; SizeArea_mm2: 1.28; SizeX_mm: 1.6; SizeY_mm: 0.8; SizeZ_mm: 1; EIA_Code: E24; U/M: EA; AEC Category: Q200
R43 = CRCW1206374KFKEA: RES, 374 k, 1%, 0.25 W, 1206; Manufacturer: Vishay-Dale; CompType: Resistor; Value: 374k; Res_ohm: 374000; Tolerance_%: 1; Power_W: 0.25; Value2: 0.25W; VDC_V: 200; TempCo: 100 ppm/C; EIA_Code: E96; U/M: EA
R44 R45 = CR0603-JW-472GLF: RES, 4.7 k, 5%, 0.1 W, 0603; Manufacturer: Bourns; CompType: Resistor; Value: 4.7k; Res_ohm: 4700; Value_Code: 4k70; Tolerance_%: 5; Power_W: 0.1; Value2: 0.1W; VDC_V: 50; TempCo: 200 ppm/C; EIA_Code: E24; U/M: EA
R48 = CRCW0603147KFKEA: RES, 147 k, 1%, 0.1 W, 0603; Manufacturer: Vishay-Dale; CompType: Resistor; Value: 147k; Res_ohm: 147000; Tolerance_%: 1; Power_W: 0.1; Value2: 0.1W; VDC_V: 75; TempCo: 100 ppm/C; SizeArea_mm2: 1.28; SizeX_mm: 1.6; SizeY_mm: 0.8; EIA_Code: E96; U/M: EA; AEC Category: Q200; Green_Lifecycle: Active; Green_REACh: Passed
R49 = CRCW060310K0FKEA: RES, 10.0 k, 1%, 0.1 W, 0603; Manufacturer: Vishay-Dale; CompType: Resistor; Value: 10.0k; Res_ohm: 10000; Value_Code: 10k0; Tolerance_%: 1; Power_W: 0.1; Value2: 0.1W; VDC_V: 75; TempCo: 100 ppm/C; SizeArea_mm2: 1.28; SizeX_mm: 1.6; SizeY_mm: 0.8; EIA_Code: E96; U/M: EA; AEC Category: Q200; Green_Lifecycle: Active; Green_REACh: Passed
R50 = CRCW060316K9FKEA: RES, 16.9 k, 1%, 0.1 W, 0603; Manufacturer: Vishay-Dale; CompType: Resistor; Value: 16.9k; Res_ohm: 16900; Value_Code: 16k9; Tolerance_%: 1; Power_W: 0.1; Value2: 0.1W; VDC_V: 75; TempCo: 100 ppm/C; SizeArea_mm2: 1.28; SizeX_mm: 1.6; SizeY_mm: 0.8; EIA_Code: E96; U/M: EA; AEC Category: Q200; Green_Lifecycle: Active; Green_REACh: Passed
R51 R63 = CMP-0022010-4: RES, 113 k, 1%, 0.1 W, AEC-Q200 Grade 0, 0603; Manufacturer: Vishay-Dale; Power_W: 100mW; TempCo: 100 ppm/C; Value: 113k; EIA_Code: E96; SizeX_mm: 1.6; SizeY_mm: 0.8; SizeZ_mm: 1; Value2: 0.1W; SizeArea_mm2: 1.28; AEC Qualified: Y; VDC_V: 75V; AEC Category: Q200; AEC Grade: 0
R52 R53 = CRCW080510R0JNEA: RES, 10, 5%, 0.125 W, 0805; Manufacturer: Vishay-Dale; CompType: Resistor; Value: 10; Value_Code: 10R0; Tolerance_%: 5; Power_W: 0.125; Value2: 0.125W; VDC_V: 150; TempCo: 200 ppm/C; EIA_Code: E24; U/M: EA
R56 = CMP-0023630-3: RES, 100 k, 0.1%, 0.1 W, 0603; Manufacturer: Yageo America; Power_W: 100mW; TempCo: 25 ppm/C; U/M: EA; Value: 100k; EIA_Code: E192; SizeX_mm: 1.6; SizeY_mm: 0.8; SizeZ_mm: 1; Value2: 0.1W; SizeArea_mm2: 1.28; VDC_V: 75V; AEC Category: Q200
R60 R61 = CRCW08054R70JNEA: RES, 4.7, 5%, 0.125 W, 0805; Manufacturer: Vishay-Dale; CompType: Resistor; Value: 4.7; Value_Code: 4R70; Tolerance_%: 5; Power_W: 0.125; Value2: 0.125W; VDC_V: 150; TempCo: 200 ppm/C; EIA_Code: E24; U/M: EA
R62 = CMP-0023252-5: RES, 6.81 k, 1%, 0.1 W, 0603; Manufacturer: Yageo; Power_W: 100mW; TempCo: 100 ppm/C; Value_Code: 6k81; Value: 6.81k; EIA_Code: E96; SizeX_mm: 1.6; SizeY_mm: 0.8; SizeZ_mm: 1; Value2: 0.1W; SizeArea_mm2: 1.28; AEC Qualified: N; VDC_V: 75V; AEC Category: Q200; SizeAreaWB_mm2: 4.68
R65 = CMP-0015849-2: RES, 0.0005, 1%, 2 W, 2512; Manufacturer: Vishay-Dale; Power_W: 2W; TempCo: 400 ppm/C; Value_Code: L5000; U/M: EA; Value: 0.0005; Res_ohm: 500µ; SizeX_mm: 6.35; SizeY_mm: 3.18; SizeZ_mm: 0.89; SizeArea_mm2: 20.193; AEC Qualified: N; AEC Category: Q200
R66 R78 = CMP-0022004-4: RES, 10.0, 1%, 0.25 W, AEC-Q200 Grade 0, 0603; Manufacturer: Vishay-Dale; Power_W: 250mW; TempCo: 100 ppm/C; Value_Code: 10R0; Value: 10.0; EIA_Code: E96; Res_ohm: 10; SizeX_mm: 1.6; SizeY_mm: 0.8; SizeZ_mm: 1; Value2: 0.25W; SizeArea_mm2: 1.28; AEC Qualified: Y; VDC_V: 75V; AEC Category: Q200; AEC Grade: 0
R67 = CMP-0020980-3: RES, 1.00 M, 1%, 0.125 W, AEC-Q200 Grade 0, 0805; Manufacturer: Vishay-Dale; Power_W: 125mW; TempCo: 100 ppm/C; Value_Code: 1M00; Value: 1.00Meg; EIA_Code: E96; Res_ohm: 1M; SizeX_mm: 2; SizeY_mm: 1.25; SizeZ_mm: 1.45; Value2: 0.125W; AEC Qualified: Y; VDC_V: 150V; AEC Category: Q200; SizeArea_mm2: 2.5; AEC Grade: 0
R68 = CMP-0022731-2: RES, 1.00 M, 1%, 0.125 W, 0603; Manufacturer: Vishay/Beyschlag; Power_W: 125mW; TempCo: 50 ppm/C; Value_Code: 1M00; U/M: EA; Value: 1.00Meg; EIA_Code: E96; Res_ohm: 1M; SizeX_mm: 1.6; SizeY_mm: 0.8; SizeZ_mm: 1; Value2: 0.125W; SizeArea_mm2: 1.28; AEC Qualified: N; VDC_V: 75V; AEC Category: Q200
R69 = CMP-0022697-2: RES, 330 k, 1%, 0.1 W, AEC-Q200 Grade 0, 0603; Manufacturer: Panasonic; Power_W: 100mW; TempCo: 100 ppm/C; U/M: EA; Value: 330k; SizeX_mm: 1.6; SizeY_mm: 0.8; SizeZ_mm: 1; Value2: 0.1W; SizeArea_mm2: 1.28; AEC Qualified: Y; VDC_V: 75V; AEC Grade: 0; AEC Category: Q200
T1 = PQ3230: Transformer, TH; Manufacturer: Payton; SymbolCreator: Altium; U/M: EA
U2 = UCC25630DDB: Enhanced LLC Resonant Controller with Driver, DDB0014A (SOIC-14); Manufacturer: Texas Instruments; SymbolCreator: Altium; SizeArea_mm2: 59.4; SizeAreaWB_mm2: 95.2; SizeX_mm: 6; SizeY_mm: 9.9; SizeZ_mm: 1.75; CompType: IC; U/M: EA
U4 = CMP-0076214-1: Series of Adjustable Micropower Voltage Regulators, D0008A (SOIC-8); Manufacturer: Texas Instruments; Alternate PartNumber: LP2951ACM/NOPB; SizeAreaWB_mm2: 56.58; SizeArea_mm2: 30.38; SizeZ_mm: 1.75; SizeY_mm: 6.2; U/M: EA; CompType: IC; SizeX_mm: 4.9
U5 = TL431ACDBZR: Adjustable Precision Shunt Regulator, 34 ppm / degC, 100 mA, 0 to 70 degC, 3-pin SOT-23 (DBZ), Green (RoHS & no Sb/Br); Manufacturer: Texas Instruments; Alternate PartNumber: Equivalent; Initial Accuracy @ 25/deg C(%): 1; Iout/Iz(Max)(mA): 100; Min Iz for Regulation(uA): 600; Rating: Catalog; SubFamily: Shunt Voltage Reference; Temp Coeff(Typ)(ppm/ degree C): 34; VO Adj(Max)(V): 36; VO Adj(Min)(V): 2.495
U6 U12 = VO618A: Optocoupler, 5.3 kV, 50-600% CTR, TH; Manufacturer: Vishay-Semiconductor; CTR (Min): 50%; CTR (Max): 600%; Voltage_Isolation_Vrms: 5300V; SizeAreaWB_mm2: 71.064; SizeArea_mm2: 40.304; SizeX_mm: 8.8; SizeY_mm: 4.58; SizeZ_mm: 5
U7 U8 = UCC24612-1DBVR: UCC24612-1DBV, DBV0005A (SOT-23-5); Alternate PartNumber: UCC24612-1DBVT; Manufacturer: Texas Instruments; SymbolCreator: Altium; SizeArea_mm2: 8.12; SizeAreaWB_mm2: 14.82; SizeX_mm: 2.8; SizeY_mm: 2.9; SizeZ_mm: 1.45; CompType: IC; U/M: EA
U10 = CMP-0070878-1: Micropower 100 mA Ultra Low-Dropout Regulator, 5-pin SOT-23, Pb-Free; Manufacturer: Texas Instruments; PartNumber: LP29681-50; CompType: LDO IC; PowerWise: N; PackageTopMarking: L05B*XTT
U11 = CMP-0065409-1: SINGLE DIFFERENTIAL COMPARATOR, DBV0005A (SOT-23-5); Alternate PartNumber: TL331IDBVT; Alternate Manufacturer: Texas Instruments; Green_Lifecycle: Active; SizeAreaWB_mm2: 14.82; Green_REACh: Passed; U/M: EA; SizeZ_mm: 1.45; SizeX_mm: 2.8; SizeY_mm: 2.9; SizeArea_mm2: 8.12; CompType: IC
U14 = CMP-0013228-2: Bidirectional, Low- and High-Side Measurement, Multichannel, Voltage Output, Current-Sense Amplifier, DBV0006A (SOT-6); Manufacturer: Texas Instruments; SizeX_mm: 2.8; SizeY_mm: 2.9; CompType: IC; SizeZ_mm: 1.45; SizeArea_mm2: 8.12; SizeAreaWB_mm2: 14.82; U/M: EA

## Sheet TIDA-010015_Hardware.SchDoc: Hardware
size 431 x 279 mm; Date: Not shown in title block; ApprovedBy: Not shown in title block; CheckedBy: Not shown in title block; Author: Not shown in title block; CompanyName: Not shown in title block; DrawnBy: Ramkumar S; Engineer: Ramkumar S; Organization: Not shown in title block; Address1: Not shown in title block; Address2: Not shown in title block; Address3: Not shown in title block; Address4: Not shown in title block; DocumentNumber: 1; Revision: Use project parameter SCH_Rev; SheetNumber: 4; SheetTotal: 4; PageSetup: Record=PageOptions¦CenterHorizontal=True¦CenterVertical=True¦PrintScale=1.00¦XCorrection=1.00¦YCorrection=1.00¦PrintKind=0¦BorderSize=5000000¦LeftOffset=0¦BottomOffset=0¦Orientation=2¦PaperLength=1000¦PaperWidth=1000¦Scale=100¦PaperSource=15¦PrintQuality=600¦MediaType=1¦DitherType=10¦PaperKind=Letter¦PrintScaleMode=1
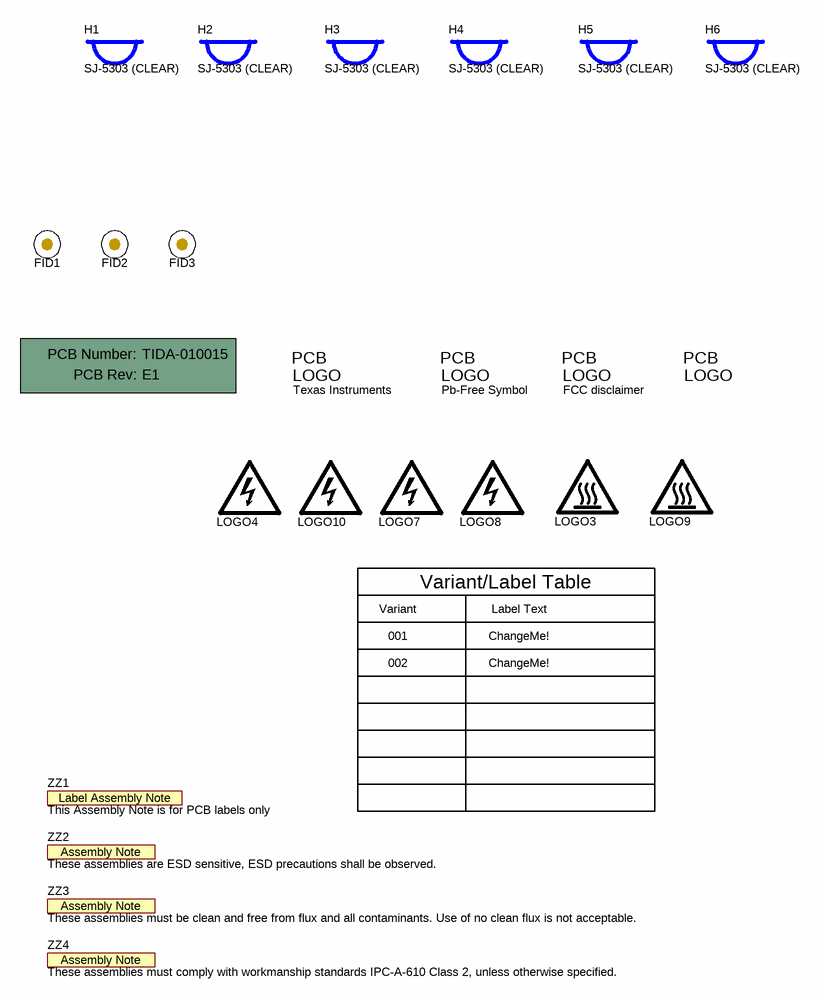
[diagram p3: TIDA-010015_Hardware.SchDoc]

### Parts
!PCB1  Printed Circuit Board  (value not drawn)  (mechanical)
FID1  Fiducial  [Fiducial10-20]  (value not drawn)
FID2  Fiducial  [Fiducial10-20]  (value not drawn)
FID3  Fiducial  [Fiducial10-20]  (value not drawn)
H1  SJ-5303 (CLEAR)  [Bumpon_SJ5003Transparent]
H2  SJ-5303 (CLEAR)  [Bumpon_SJ5003Transparent]
H3  SJ-5303 (CLEAR)  [Bumpon_SJ5003Transparent]
H4  SJ-5303 (CLEAR)  [Bumpon_SJ5003Transparent]
H5  SJ-5303 (CLEAR)  [Bumpon_SJ5003Transparent]
H6  SJ-5303 (CLEAR)  [Bumpon_SJ5003Transparent]
Logo1  Pb-Free Symbol  [Pb-Free_Overlay_Small]  (no BOM)
Logo2  ESD Susceptible  [ESD_Overlay_Small]  (value not drawn)  (no BOM)
LOGO3  CAUTION HOT SURFACE  [IEC_HotSurface_Small]  (value not drawn)  (no BOM)
LOGO4  DANGER HIGH VOLTAGE  [IEC_HighVoltage_Small]  (value not drawn)  (no BOM)
Logo5  Texas Instruments  [TI_Stacked_Overlay_Small]  (no BOM)
Logo6  FCC disclaimer  [FCC_disclaimer]  (no BOM)
LOGO7  DANGER HIGH VOLTAGE  [IEC_HighVoltage_Small]  (value not drawn)  (no BOM)
LOGO8  DANGER HIGH VOLTAGE  [IEC_HighVoltage_Small]  (value not drawn)  (no BOM)
LOGO9  CAUTION HOT SURFACE  [IEC_HotSurface_Small]  (value not drawn)  (no BOM)
LOGO10  DANGER HIGH VOLTAGE  [IEC_HighVoltage_Small]  (value not drawn)  (no BOM)
ZZ1  This Assembly Note is for PCB labels only  [AssemblyNoteLabel]  (no BOM)
ZZ2  These assemblies are ESD sensitive, ESD precautions shall be observed.  [AssemblyNote]  (no BOM)
ZZ3  These assemblies must be clean and free from flux and all contaminants. Use of no clean flux is not acceptable.  [AssemblyNote]  (no BOM)
ZZ4  These assemblies must comply with workmanship standards IPC-A-610 Class 2, unless otherwise specified.  [AssemblyNote]  (no BOM)

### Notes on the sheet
- Variant
- Variant/Label Table
- Label Text
- 001
- 002
- ChangeMe!

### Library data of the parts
!PCB1 = PCB: Manufacturer: Any; PartNumber: TIDA-010015; SymbolCreator: a0412235
FID1-FID3 = Fiducial: Fiducial mark.  There is nothing to buy or mount.; SymbolCreator: codlsc
H1-H6 = SJ-5303 (CLEAR): Bumpon, Hemisphere, 0.44 X 0.20, Clear; Manufacturer: 3M; SymbolCreator: a0412235
Logo1 = Pb-Free: SymbolCreator: a0412235
Logo2 = ESD_Susceptible: ESD Susceptible Symbol; SymbolCreator: a0412235
LOGO3 LOGO9 = IEC_HotSurface: as LOGO?#6 on sheet TIDA-010015-LLC
LOGO4 LOGO7 LOGO8 LOGO10 = IEC_HighVoltage: as LOGO?#5 on sheet TIDA-010015-LLC
Logo5 = TI_Logo: Texas Instrument Corporate Signature; SymbolCreator: codlsc
Logo6 = FCC_disclaimer: SymbolCreator: codlsc
ZZ1 = AssemblyNoteLabel: SymbolCreator: a0412235
ZZ2-ZZ4 = AssemblyNote: SymbolCreator: codlsc

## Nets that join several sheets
390V: TIDA-010015_PFC (7 pins), TIDA-010015-LLC (5 pins)
AUX_15V: TIDA-010015_PFC (9 pins), TIDA-010015-LLC (5 pins)
PGND: TIDA-010015_PFC (58 pins), TIDA-010015-LLC (32 pins)
NetA: TIDA-010015_PFC (D9.1 D10.1 R28.1), TIDA-010015-LLC (R31.1)

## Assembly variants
001: not fitted FID1 FID2 FID3 R39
